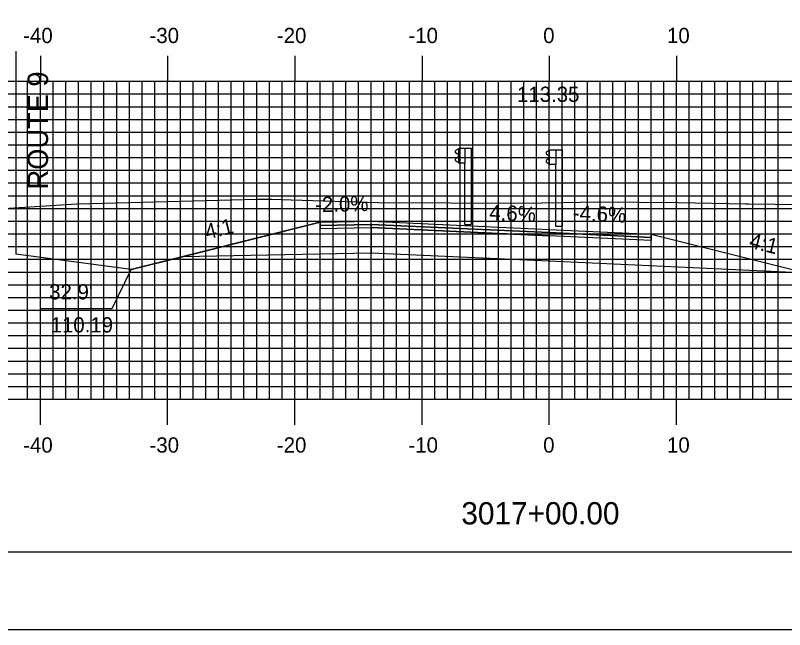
# Model space of a CAD drawing. Extents: x 1685586 to 1685929, y 461260 to 461480.
# Drawn here: x 1685709.8 to 1685770.2, y 461260 to 461308.3 of the extents above; entities that cross this region are included whole.
import ezdxf

# ---------------------------------------------------------------- set-up
doc = ezdxf.new("R2010")
doc.units = 0
for name, color, linetype in [('ANNOTATION', 7, 'Continuous'), ('BORDER', 7, 'Continuous'), ('D_Roadway_Centerline', 7, 'Continuous'), ('D_Roadway_Centerline_Text', 7, 'Continuous'), ('D_Roadway_Edge_Shoulder', 7, 'Continuous'), ('D_Roadway_Edge_TW', 7, 'Continuous'), ('D_Roadway_Pavement', 7, 'Continuous'), ('D_Roadway_SlopeLines', 7, 'Continuous'), ('D_Roadway_SubGrade', 7, 'Continuous'), ('H_V ANNOTATION', 7, 'Continuous'), ('M_Guardrail', 7, 'Continuous'), ('M_Roadway_Centerline', 7, 'Continuous'), ('MAJOR', 7, 'Continuous'), ('MINOR', 7, 'Continuous'), ('PLOT BOUNDARY', 7, 'Continuous'), ('S_Roadway_Centerline', 7, 'Continuous')]:
    doc.layers.add(name, color=color, linetype=linetype)

msp = doc.modelspace()

# ---------------------------------------------------------------- linework, layer by layer
at = {"layer": 'ANNOTATION'}
msp.add_lwpolyline([(1685711.697, 461285.191), (1685717.389, 461285.191), (1685718.873, 461288.264)], dxfattribs=at)
at = {"layer": 'BORDER'}
msp.add_lwpolyline([(1685602.142, 461266.072), (1685922.142, 461266.072), (1685922.142, 461476.072), (1685602.142, 461476.072)], close=True, dxfattribs=at)
at = {"layer": 'D_Roadway_Centerline'}
msp.add_lwpolyline([(1685718.873, 461288.264), (1685722.873, 461289.264), (1685733.742, 461291.981), (1685737.742, 461292.061), (1685751.742, 461291.417), (1685759.742, 461291.049), (1685771.997, 461287.986), (1685775.997, 461286.986), (1685826.267, 461288.625)], dxfattribs=at)
at = {"layer": 'D_Roadway_Edge_Shoulder'}
for points in [[(1685737.742, 461292.061), (1685733.742, 461291.981), (1685733.742, 461291.731), (1685737.742, 461291.811)], [(1685737.742, 461291.811), (1685733.742, 461291.731), (1685733.742, 461291.481), (1685737.742, 461291.561)], [(1685751.742, 461291.417), (1685759.742, 461291.049), (1685759.742, 461290.799), (1685751.742, 461291.167)], [(1685751.742, 461291.167), (1685759.742, 461290.799), (1685759.742, 461290.549), (1685751.742, 461290.917)]]:
    msp.add_lwpolyline(points, close=True, dxfattribs=at)
at = {"layer": 'D_Roadway_Edge_TW'}
msp.add_lwpolyline([(1685737.742, 461292.061), (1685751.742, 461291.417), (1685751.742, 461291.167), (1685737.742, 461291.811)], close=True, dxfattribs=at)
at = {"layer": 'D_Roadway_Pavement'}
msp.add_lwpolyline([(1685737.742, 461291.811), (1685751.742, 461291.167), (1685751.742, 461290.917), (1685737.742, 461291.561)], close=True, dxfattribs=at)
for points in [[(1685737.742, 461291.811), (1685737.742, 461291.561)], [(1685737.742, 461291.811), (1685737.742, 461291.561)], [(1685751.742, 461291.167), (1685751.742, 461290.917)], [(1685751.742, 461291.167), (1685751.742, 461290.917)], [(1685751.742, 461291.167), (1685751.742, 461290.917)]]:
    msp.add_lwpolyline(points, dxfattribs=at)
at = {"layer": 'D_Roadway_SlopeLines'}
msp.add_line((1685718.873, 461288.264), (1685709.812, 461289.488), dxfattribs=at)
for points in [[(1685733.742, 461291.981), (1685718.873, 461288.264)], [(1685759.742, 461291.049), (1685775.997, 461286.986)]]:
    msp.add_lwpolyline(points, dxfattribs=at)
at = {"layer": 'D_Roadway_SubGrade'}
msp.add_line((1685709.812, 461305.439), (1685709.812, 461289.488), dxfattribs=at)
for points in [[(1685737.742, 461289.561), (1685722.873, 461289.264), (1685733.742, 461291.981), (1685733.742, 461291.731), (1685737.742, 461291.811), (1685737.742, 461291.561)], [(1685737.742, 461291.561), (1685751.742, 461290.917), (1685751.742, 461288.917), (1685737.742, 461289.561)], [(1685751.742, 461290.917), (1685751.742, 461291.167), (1685759.742, 461290.799), (1685759.742, 461291.049), (1685771.997, 461287.986), (1685751.742, 461288.917)]]:
    msp.add_lwpolyline(points, close=True, dxfattribs=at)
at = {"layer": 'M_Guardrail'}
for p, q in [((1685744.522, 461297.711), (1685744.378, 461297.611)), ((1685744.62, 461297.732), (1685744.538, 461297.717)), ((1685744.62, 461297.805), (1685745.11, 461297.805)), ((1685744.62, 461296.638), (1685744.62, 461297.805)), ((1685745.11, 461297.805), (1685745.602, 461297.805)), ((1685745.11, 461297.805), (1685745.11, 461296.638)), ((1685745.602, 461297.805), (1685745.602, 461291.805)), ((1685751.769, 461297.687), (1685752.258, 461297.687)), ((1685751.769, 461296.52), (1685751.769, 461297.687)), ((1685752.258, 461297.687), (1685752.75, 461297.687)), ((1685752.258, 461297.687), (1685752.258, 461296.52)), ((1685752.75, 461297.687), (1685752.75, 461291.687)), ((1685744.378, 461297.467), (1685744.573, 461297.331)), ((1685744.573, 461297.112), (1685744.378, 461296.975)), ((1685744.607, 461297.267), (1685744.607, 461297.176)), ((1685751.67, 461297.592), (1685751.527, 461297.492)), ((1685751.527, 461297.349), (1685751.722, 461297.213)), ((1685751.769, 461297.614), (1685751.687, 461297.599)), ((1685751.756, 461297.149), (1685751.756, 461297.058)), ((1685744.378, 461296.832), (1685744.522, 461296.732)), ((1685744.538, 461296.725), (1685744.62, 461296.711)), ((1685745.11, 461296.638), (1685744.62, 461296.638)), ((1685745.11, 461291.805), (1685745.11, 461296.638)), ((1685751.722, 461296.993), (1685751.527, 461296.857)), ((1685751.527, 461296.714), (1685751.67, 461296.614)), ((1685751.687, 461296.607), (1685751.769, 461296.593)), ((1685752.258, 461296.52), (1685751.769, 461296.52)), ((1685752.258, 461291.687), (1685752.258, 461296.52)), ((1685745.11, 461291.805), (1685745.602, 461291.805)), ((1685752.258, 461291.687), (1685752.75, 461291.687))]:
    msp.add_line(p, q, dxfattribs=at)
for centre, major_axis, start_param, end_param in [((1685744.545, 461297.677), (-0.0417, 0), 4.886922, 5.323254), ((1685744.428, 461297.539), (-0.0877, 0), 5.323254, 7.243116), ((1685744.528, 461297.267), (0.0789, 0), 0, 0.959931), ((1685744.528, 461297.176), (0.0789, 0), 5.323254, 6.283185), ((1685751.577, 461297.421), (-0.0877, 0), 5.323254, 7.243116), ((1685751.694, 461297.558), (-0.0417, 0), 4.886922, 5.323254), ((1685751.677, 461297.149), (0.0789, 0), 0, 0.959931), ((1685751.677, 461297.058), (0.0789, 0), 5.323254, 6.283185), ((1685744.428, 461296.904), (-0.0877, 0), 5.323254, 7.243116), ((1685744.545, 461296.766), (-0.0417, 0), 0.959931, 1.396263), ((1685751.577, 461296.786), (-0.0877, 0), 5.323254, 7.243116), ((1685751.694, 461296.648), (-0.0417, 0), 0.959931, 1.396263)]:
    msp.add_ellipse(centre, major_axis=major_axis, ratio=0.995501, start_param=start_param, end_param=end_param, dxfattribs=at)
at = {"layer": 'MAJOR'}
for p, q in [((1685711.742, 461305.076), (1685711.742, 461303.072)), ((1685721.742, 461305.076), (1685721.742, 461303.072)), ((1685731.742, 461305.076), (1685731.742, 461303.072)), ((1685741.742, 461305.076), (1685741.742, 461303.072)), ((1685751.742, 461305.076), (1685751.742, 461303.072)), ((1685761.742, 461305.076), (1685761.742, 461303.072)), ((1685611.742, 461303.072), (1685891.742, 461303.072)), ((1685611.742, 461303.072), (1685891.742, 461303.072)), ((1685711.742, 461278.072), (1685711.742, 461303.072)), ((1685721.742, 461278.072), (1685721.742, 461303.072)), ((1685731.742, 461278.072), (1685731.742, 461303.072)), ((1685741.742, 461278.072), (1685741.742, 461303.072)), ((1685751.742, 461278.072), (1685751.742, 461303.072)), ((1685761.742, 461278.072), (1685761.742, 461303.072)), ((1685611.742, 461298.072), (1685891.742, 461298.072)), ((1685611.742, 461293.072), (1685891.742, 461293.072)), ((1685611.742, 461288.072), (1685891.742, 461288.072)), ((1685611.742, 461283.072), (1685891.742, 461283.072)), ((1685611.742, 461278.072), (1685891.742, 461278.072)), ((1685611.742, 461278.072), (1685891.742, 461278.072)), ((1685711.742, 461276.068), (1685711.742, 461278.072)), ((1685721.742, 461276.068), (1685721.742, 461278.072)), ((1685731.742, 461276.068), (1685731.742, 461278.072)), ((1685741.742, 461276.068), (1685741.742, 461278.072)), ((1685751.742, 461276.068), (1685751.742, 461278.072)), ((1685761.742, 461276.068), (1685761.742, 461278.072))]:
    msp.add_line(p, q, dxfattribs=at)
at = {"layer": 'MINOR'}
for p, q in [((1685710.742, 461278.072), (1685710.742, 461303.072)), ((1685712.742, 461278.072), (1685712.742, 461303.072)), ((1685713.742, 461278.072), (1685713.742, 461303.072)), ((1685714.742, 461278.072), (1685714.742, 461303.072)), ((1685715.742, 461278.072), (1685715.742, 461303.072)), ((1685716.742, 461278.072), (1685716.742, 461303.072)), ((1685717.742, 461278.072), (1685717.742, 461303.072)), ((1685718.742, 461278.072), (1685718.742, 461303.072)), ((1685719.742, 461278.072), (1685719.742, 461303.072)), ((1685720.742, 461278.072), (1685720.742, 461303.072)), ((1685722.742, 461278.072), (1685722.742, 461303.072)), ((1685723.742, 461278.072), (1685723.742, 461303.072)), ((1685724.742, 461278.072), (1685724.742, 461303.072)), ((1685725.742, 461278.072), (1685725.742, 461303.072)), ((1685726.742, 461278.072), (1685726.742, 461303.072)), ((1685727.742, 461278.072), (1685727.742, 461303.072)), ((1685728.742, 461278.072), (1685728.742, 461303.072)), ((1685729.742, 461278.072), (1685729.742, 461303.072)), ((1685730.742, 461278.072), (1685730.742, 461303.072)), ((1685732.742, 461278.072), (1685732.742, 461303.072)), ((1685733.742, 461278.072), (1685733.742, 461303.072)), ((1685734.742, 461278.072), (1685734.742, 461303.072)), ((1685735.742, 461278.072), (1685735.742, 461303.072)), ((1685736.742, 461278.072), (1685736.742, 461303.072)), ((1685737.742, 461278.072), (1685737.742, 461303.072)), ((1685738.742, 461278.072), (1685738.742, 461303.072)), ((1685739.742, 461278.072), (1685739.742, 461303.072)), ((1685740.742, 461278.072), (1685740.742, 461303.072)), ((1685742.742, 461278.072), (1685742.742, 461303.072)), ((1685743.742, 461278.072), (1685743.742, 461303.072)), ((1685744.742, 461278.072), (1685744.742, 461303.072)), ((1685745.742, 461278.072), (1685745.742, 461303.072)), ((1685746.742, 461278.072), (1685746.742, 461303.072)), ((1685747.742, 461278.072), (1685747.742, 461303.072)), ((1685748.742, 461278.072), (1685748.742, 461303.072)), ((1685749.742, 461278.072), (1685749.742, 461303.072)), ((1685750.742, 461278.072), (1685750.742, 461303.072)), ((1685752.742, 461278.072), (1685752.742, 461303.072)), ((1685753.742, 461278.072), (1685753.742, 461303.072)), ((1685754.742, 461278.072), (1685754.742, 461303.072)), ((1685755.742, 461278.072), (1685755.742, 461303.072)), ((1685756.742, 461278.072), (1685756.742, 461303.072)), ((1685757.742, 461278.072), (1685757.742, 461303.072)), ((1685758.742, 461278.072), (1685758.742, 461303.072)), ((1685759.742, 461278.072), (1685759.742, 461303.072)), ((1685760.742, 461278.072), (1685760.742, 461303.072)), ((1685762.742, 461278.072), (1685762.742, 461303.072)), ((1685763.742, 461278.072), (1685763.742, 461303.072)), ((1685764.742, 461278.072), (1685764.742, 461303.072)), ((1685765.742, 461278.072), (1685765.742, 461303.072)), ((1685766.742, 461278.072), (1685766.742, 461303.072)), ((1685767.742, 461278.072), (1685767.742, 461303.072)), ((1685768.742, 461278.072), (1685768.742, 461303.072)), ((1685769.742, 461278.072), (1685769.742, 461303.072)), ((1685611.742, 461302.072), (1685891.742, 461302.072)), ((1685611.742, 461301.072), (1685891.742, 461301.072)), ((1685611.742, 461300.072), (1685891.742, 461300.072)), ((1685611.742, 461299.072), (1685891.742, 461299.072)), ((1685611.742, 461297.072), (1685891.742, 461297.072)), ((1685611.742, 461296.072), (1685891.742, 461296.072)), ((1685611.742, 461295.072), (1685891.742, 461295.072)), ((1685611.742, 461294.072), (1685891.742, 461294.072)), ((1685611.742, 461292.072), (1685891.742, 461292.072)), ((1685611.742, 461291.072), (1685891.742, 461291.072)), ((1685611.742, 461290.072), (1685891.742, 461290.072)), ((1685611.742, 461289.072), (1685891.742, 461289.072)), ((1685611.742, 461287.072), (1685891.742, 461287.072)), ((1685611.742, 461286.072), (1685891.742, 461286.072)), ((1685611.742, 461285.072), (1685891.742, 461285.072)), ((1685611.742, 461284.072), (1685891.742, 461284.072)), ((1685611.742, 461282.072), (1685891.742, 461282.072)), ((1685611.742, 461281.072), (1685891.742, 461281.072)), ((1685611.742, 461280.072), (1685891.742, 461280.072)), ((1685611.742, 461279.072), (1685891.742, 461279.072))]:
    msp.add_line(p, q, dxfattribs=at)
at = {"layer": 'PLOT BOUNDARY'}
msp.add_lwpolyline([(1685585.956, 461259.954), (1685925.956, 461259.954), (1685925.956, 461479.954), (1685585.956, 461479.954)], close=True, dxfattribs=at)
at = {"layer": 'S_Roadway_Centerline'}
msp.add_lwpolyline([(1685708.034, 461293.011), (1685714.607, 461293.422), (1685728.826, 461293.807), (1685729.844, 461293.808), (1685729.924, 461293.804), (1685731.445, 461293.758), (1685738.288, 461293.544), (1685749.674, 461293.49), (1685755.651, 461293.58), (1685761.864, 461293.531), (1685767.186, 461293.43), (1685767.401, 461293.431), (1685771.594, 461293.379)], dxfattribs=at)

# ---------------------------------------------------------------- texts
at = {"layer": 'ANNOTATION'}
for s, height, rotation, p in [('ROUTE 9', 1.6, 90, (1685712.344, 461294.568)), ('-2.0%', 1.2, 1.14576, (1685733.349, 461292.774)), ('4.6%', 1.2, 357.36625, (1685747.006, 461292.171)), ('-4.6%', 1.2, 357.36625, (1685753.568, 461292.136)), ('4:1', 1.2, 14.03624, (1685724.843, 461290.618)), ('4:1', 1.2, 345.96376, (1685767.376, 461290.003))]:
    msp.add_text(s, height=height, rotation=rotation, dxfattribs=at).set_placement(p)
for s, p in [("32.9' ", (1685712.432, 461285.917)), ('110.19', (1685712.545, 461283.317))]:
    msp.add_text(s, height=1.2, dxfattribs=at).set_placement(p)
at = {"layer": 'D_Roadway_Centerline_Text'}
msp.add_text('113.35', height=1.2, dxfattribs=at).set_placement((1685749.201, 461301.447))
at = {"layer": 'H_V ANNOTATION'}
for s, height, p in [('-40', 1.2, (1685710.394, 461306.072)), ('-30', 1.2, (1685720.319, 461306.072)), ('-20', 1.2, (1685730.329, 461306.072)), ('-10', 1.2, (1685740.672, 461306.072)), ('0', 1.2, (1685751.261, 461306.072)), ('10', 1.2, (1685760.993, 461306.072)), ('-40', 1.2, (1685710.394, 461273.872)), ('-30', 1.2, (1685720.319, 461273.872)), ('-20', 1.2, (1685730.329, 461273.872)), ('-10', 1.2, (1685740.672, 461273.872)), ('0', 1.2, (1685751.261, 461273.872)), ('10', 1.2, (1685760.993, 461273.872)), ('3017+00.00', 1.75, (1685744.829, 461268.228))]:
    msp.add_text(s, height=height, dxfattribs=at).set_placement(p)
at = {"layer": 'M_Roadway_Centerline'}
for s, p in [('C', (1685729.839, 461293.808)), ('L', (1685729.844, 461293.801))]:
    msp.add_text(s, height=0.0146, dxfattribs=at).set_placement(p)

doc.saveas('drawing.dxf')
